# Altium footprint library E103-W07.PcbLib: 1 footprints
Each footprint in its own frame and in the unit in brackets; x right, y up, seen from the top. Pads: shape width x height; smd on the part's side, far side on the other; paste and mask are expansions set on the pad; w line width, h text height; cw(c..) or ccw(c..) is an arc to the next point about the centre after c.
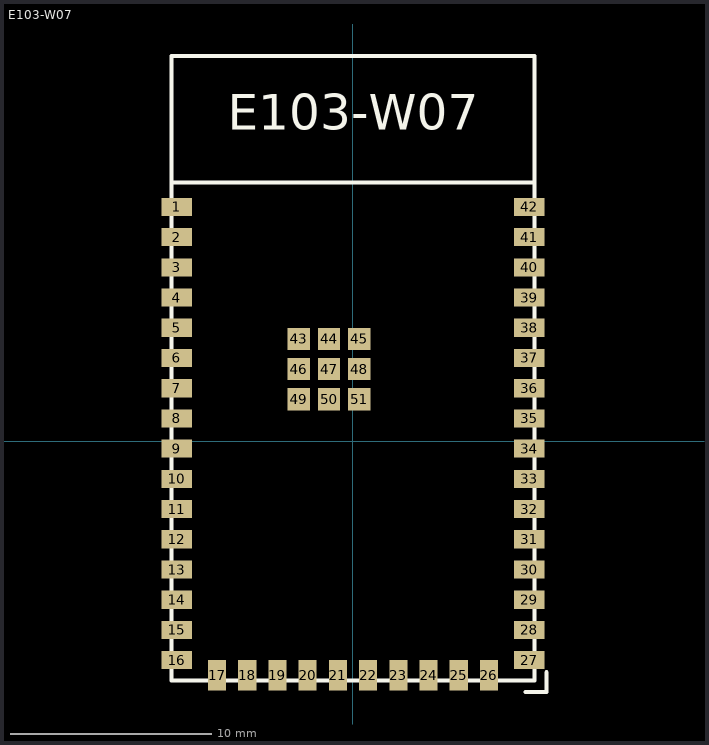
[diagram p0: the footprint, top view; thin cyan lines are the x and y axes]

## E103-W07 [mm]
pads (51):
  rect 1.5x0.9 smd: 1(-8.75,11.625) 2(-8.75,10.125) 3(-8.75,8.625) 4(-8.75,7.125) 5(-8.75,5.625) 6(-8.75,4.125) 7(-8.75,2.625) 8(-8.75,1.125) 9(-8.75,-0.375) 10(-8.75,-1.875) 11(-8.75,-3.375) 12(-8.75,-4.875) 13(-8.75,-6.375) 14(-8.75,-7.875) 15(-8.75,-9.375) 16(-8.75,-10.875) 27(8.75,-10.875) 28(8.75,-9.375) 29(8.75,-7.875) 30(8.75,-6.375) 31(8.75,-4.875) 32(8.75,-3.375) 33(8.75,-1.875) 34(8.75,-0.375) 35(8.75,1.125) 36(8.75,2.625) 37(8.75,4.125) 38(8.75,5.625) 39(8.75,7.125) 40(8.75,8.625) 41(8.75,10.125) 42(8.75,11.625)
  rect 0.9x1.5 smd: 17(-6.75,-11.625) 18(-5.25,-11.625) 19(-3.75,-11.625) 20(-2.25,-11.625) 21(-0.75,-11.625) 22(0.75,-11.625) 23(2.25,-11.625) 24(3.75,-11.625) 25(5.25,-11.625) 26(6.75,-11.625)
  rect 1.1x1.1 smd: 43(-2.69,5.075) 44(-1.19,5.075) 45(0.31,5.075) 46(-2.69,3.575) 47(-1.19,3.575) 48(0.31,3.575) 49(-2.69,2.075) 50(-1.19,2.075) 51(0.31,2.075)
Top Overlay:
  lines w0.2: 8.56,-12.465 9.6,-12.465 9.6,-11.475 ; -9,12.825 -9,19.125 9,19.125 9,12.825 ; -9,12.825 -9,-11.875 9,-11.875 9,12.825 ; -9,12.825 9,12.825
  text "E103-W07" at -6.223,14.892 h3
